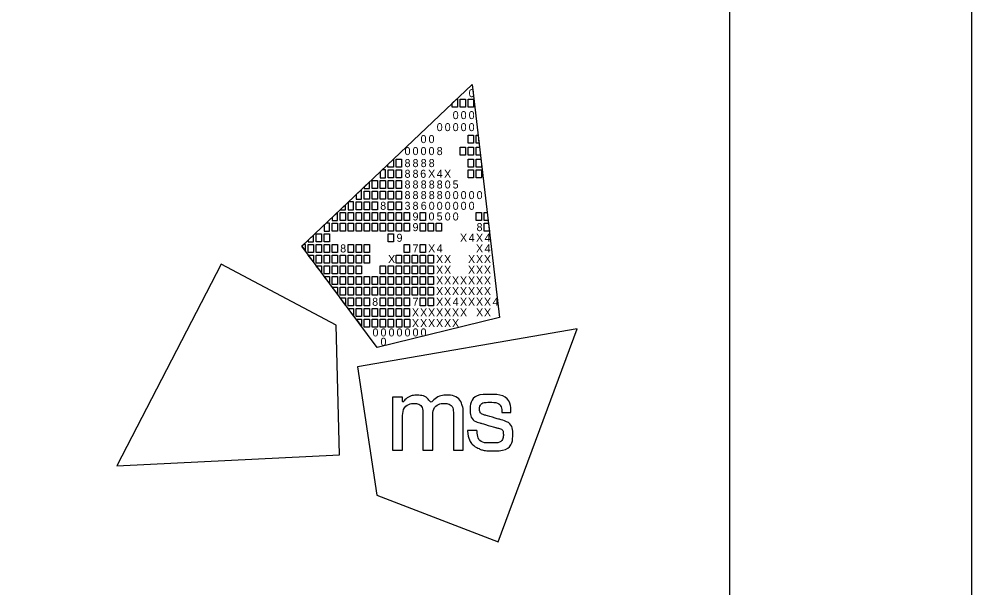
# Model space of a CAD drawing. Extents: x 0 to 34, y 0 to 22.
# Drawn here: x 32.034 to 34, y 3.547 to 4.721 of the extents above; entities that cross this region are included whole.
import ezdxf

# ---------------------------------------------------------------- set-up
doc = ezdxf.new("R2010")
doc.units = 0
for name, color, linetype in [('SH_Border', 7, 'Continuous'), ('SH_Cut_Line', 7, 'Continuous'), ('SH_Data', 7, 'Continuous')]:
    doc.layers.add(name, color=color, linetype=linetype)

msp = doc.modelspace()

# ---------------------------------------------------------------- linework, layer by layer
at = {"layer": 'SH_Border'}
for p, q in [((32.6175, 4.2519), (32.9688, 4.5861)), ((32.9688, 4.5861), (32.9688, 4.5861)), ((32.9688, 4.5861), (33.0253, 4.1052)), ((32.773, 4.043), (32.6175, 4.2519)), ((33.0253, 4.1052), (32.773, 4.043))]:
    msp.add_line(p, q, dxfattribs=at)
for points in [[(1.5, 21.5), (33.5, 21.5), (33.5, 0.5), (1.5, 0.5)], [(32.9279, 4.5472), (32.9369, 4.5558), (32.9389, 4.5558), (32.9389, 4.5393), (32.9279, 4.5393)], [(32.9444, 4.5558), (32.9554, 4.5558), (32.9554, 4.5393), (32.9444, 4.5393)], [(32.9609, 4.5558), (32.9719, 4.5558), (32.9719, 4.5393), (32.9609, 4.5393)], [(32.9606, 4.4815), (32.9716, 4.4815), (32.9716, 4.465), (32.9606, 4.465)], [(32.9771, 4.4815), (32.9811, 4.4815), (32.983, 4.465), (32.9771, 4.465)], [(32.9441, 4.4567), (32.9551, 4.4567), (32.9551, 4.4402), (32.9441, 4.4402)], [(32.9606, 4.4567), (32.9716, 4.4567), (32.9716, 4.4402), (32.9606, 4.4402)], [(32.9771, 4.4567), (32.984, 4.4567), (32.9859, 4.4402), (32.9771, 4.4402)], [(32.7953, 4.4211), (32.8064, 4.4316), (32.8064, 4.4154), (32.7953, 4.4154)], [(32.8123, 4.4319), (32.8233, 4.4319), (32.8233, 4.4154), (32.8123, 4.4154)], [(32.9606, 4.4319), (32.9716, 4.4319), (32.9716, 4.4154), (32.9606, 4.4154)], [(32.9771, 4.4319), (32.9869, 4.4319), (32.9881, 4.4218), (32.9881, 4.4154), (32.9771, 4.4154)], [(32.7958, 4.4099), (32.8068, 4.4099), (32.8068, 4.3934), (32.7958, 4.3934)], [(32.8123, 4.4099), (32.8233, 4.4099), (32.8233, 4.3934), (32.8123, 4.3934)], [(32.9606, 4.4099), (32.9716, 4.4099), (32.9716, 4.3934), (32.9606, 4.3934)], [(32.9771, 4.4099), (32.9881, 4.4099), (32.9881, 4.3934), (32.9771, 4.3934)], [(32.7627, 4.3879), (32.7737, 4.3879), (32.7737, 4.3714), (32.7627, 4.3714)], [(32.7793, 4.3879), (32.7903, 4.3879), (32.7903, 4.3714), (32.7793, 4.3714)], [(32.7958, 4.3879), (32.8068, 4.3879), (32.8068, 4.3714), (32.7958, 4.3714)], [(32.8123, 4.3879), (32.8233, 4.3879), (32.8233, 4.3714), (32.8123, 4.3714)], [(32.7462, 4.3659), (32.7572, 4.3659), (32.7572, 4.3494), (32.7462, 4.3494)], [(32.7627, 4.3659), (32.7737, 4.3659), (32.7737, 4.3494), (32.7627, 4.3494)], [(32.7793, 4.3659), (32.7903, 4.3659), (32.7903, 4.3494), (32.7793, 4.3494)], [(32.7958, 4.3659), (32.8068, 4.3659), (32.8068, 4.3494), (32.7958, 4.3494)], [(32.8123, 4.3659), (32.8233, 4.3659), (32.8233, 4.3494), (32.8123, 4.3494)], [(32.7297, 4.3439), (32.7407, 4.3439), (32.7407, 4.3273), (32.7297, 4.3273)], [(32.7462, 4.3439), (32.7572, 4.3439), (32.7572, 4.3273), (32.7462, 4.3273)], [(32.7627, 4.3439), (32.7737, 4.3439), (32.7737, 4.3273), (32.7627, 4.3273)], [(32.7958, 4.3439), (32.8068, 4.3439), (32.8068, 4.3273), (32.7958, 4.3273)], [(32.8123, 4.3439), (32.8233, 4.3439), (32.8233, 4.3273), (32.8123, 4.3273)], [(32.6967, 4.3218), (32.7077, 4.3218), (32.7077, 4.3053), (32.6967, 4.3053)], [(32.7132, 4.3218), (32.7242, 4.3218), (32.7242, 4.3053), (32.7132, 4.3053)], [(32.7297, 4.3218), (32.7407, 4.3218), (32.7407, 4.3053), (32.7297, 4.3053)], [(32.7462, 4.3218), (32.7572, 4.3218), (32.7572, 4.3053), (32.7462, 4.3053)], [(32.7627, 4.3218), (32.7737, 4.3218), (32.7737, 4.3053), (32.7627, 4.3053)], [(32.7793, 4.3218), (32.7903, 4.3218), (32.7903, 4.3053), (32.7793, 4.3053)], [(32.7958, 4.3218), (32.8068, 4.3218), (32.8068, 4.3053), (32.7958, 4.3053)], [(32.8123, 4.3218), (32.8233, 4.3218), (32.8233, 4.3053), (32.8123, 4.3053)], [(32.8288, 4.3218), (32.8398, 4.3218), (32.8398, 4.3053), (32.8288, 4.3053)], [(32.8618, 4.3218), (32.8728, 4.3218), (32.8728, 4.3053), (32.8618, 4.3053)], [(32.9771, 4.3218), (32.9881, 4.3218), (32.9881, 4.3053), (32.9771, 4.3053)], [(32.9935, 4.3218), (32.9998, 4.3218), (33.0018, 4.3053), (32.9935, 4.3053)], [(32.6802, 4.2998), (32.6912, 4.2998), (32.6912, 4.2833), (32.6802, 4.2833)], [(32.6967, 4.2998), (32.7077, 4.2998), (32.7077, 4.2833), (32.6967, 4.2833)], [(32.7132, 4.2998), (32.7242, 4.2998), (32.7242, 4.2833), (32.7132, 4.2833)], [(32.7297, 4.2998), (32.7407, 4.2998), (32.7407, 4.2833), (32.7297, 4.2833)], [(32.7462, 4.2998), (32.7572, 4.2998), (32.7572, 4.2833), (32.7462, 4.2833)], [(32.7627, 4.2998), (32.7737, 4.2998), (32.7737, 4.2833), (32.7627, 4.2833)], [(32.7793, 4.2998), (32.7903, 4.2998), (32.7903, 4.2833), (32.7793, 4.2833)], [(32.7958, 4.2998), (32.8068, 4.2998), (32.8068, 4.2833), (32.7958, 4.2833)], [(32.8123, 4.2998), (32.8233, 4.2998), (32.8233, 4.2833), (32.8123, 4.2833)], [(32.8288, 4.2998), (32.8398, 4.2998), (32.8398, 4.2833), (32.8288, 4.2833)], [(32.8618, 4.2998), (32.8728, 4.2998), (32.8728, 4.2833), (32.8618, 4.2833)], [(32.8783, 4.2998), (32.8893, 4.2998), (32.8893, 4.2833), (32.8783, 4.2833)], [(32.8947, 4.2998), (32.9057, 4.2998), (32.9057, 4.2833), (32.8947, 4.2833)], [(32.9935, 4.2998), (33.0024, 4.2998), (33.0044, 4.2833), (32.9935, 4.2833)], [(32.6471, 4.2778), (32.6581, 4.2778), (32.6581, 4.2613), (32.6471, 4.2613)], [(32.6637, 4.2778), (32.6747, 4.2778), (32.6747, 4.2613), (32.6637, 4.2613)], [(32.7958, 4.2778), (32.8068, 4.2778), (32.8068, 4.2613), (32.7958, 4.2613)], [(32.6306, 4.2558), (32.6416, 4.2558), (32.6416, 4.2393), (32.6306, 4.2393)], [(32.6471, 4.2558), (32.6581, 4.2558), (32.6581, 4.2393), (32.6471, 4.2393)], [(32.6637, 4.2558), (32.6747, 4.2558), (32.6747, 4.2393), (32.6637, 4.2393)], [(32.6802, 4.2558), (32.6912, 4.2558), (32.6912, 4.2393), (32.6802, 4.2393)], [(32.7132, 4.2558), (32.7242, 4.2558), (32.7242, 4.2393), (32.7132, 4.2393)], [(32.7297, 4.2558), (32.7407, 4.2558), (32.7407, 4.2393), (32.7297, 4.2393)], [(32.7462, 4.2558), (32.7572, 4.2558), (32.7572, 4.2393), (32.7462, 4.2393)], [(32.8288, 4.2558), (32.8398, 4.2558), (32.8398, 4.2393), (32.8288, 4.2393)], [(32.8618, 4.2558), (32.8728, 4.2558), (32.8728, 4.2393), (32.8618, 4.2393)], [(32.6306, 4.2338), (32.6416, 4.2338), (32.6416, 4.22)], [(32.6471, 4.2338), (32.6581, 4.2338), (32.6581, 4.2173), (32.6471, 4.2173)], [(32.6637, 4.2338), (32.6747, 4.2338), (32.6747, 4.2173), (32.6637, 4.2173)], [(32.6802, 4.2338), (32.6912, 4.2338), (32.6912, 4.2173), (32.6802, 4.2173)], [(32.6967, 4.2338), (32.7077, 4.2338), (32.7077, 4.2173), (32.6967, 4.2173)], [(32.7132, 4.2338), (32.7242, 4.2338), (32.7242, 4.2173), (32.7132, 4.2173)], [(32.7297, 4.2338), (32.7407, 4.2338), (32.7407, 4.2173), (32.7297, 4.2173)], [(32.7462, 4.2338), (32.7572, 4.2338), (32.7572, 4.2173), (32.7462, 4.2173)], [(32.8123, 4.2338), (32.8233, 4.2338), (32.8233, 4.2173), (32.8123, 4.2173)], [(32.8288, 4.2338), (32.8398, 4.2338), (32.8398, 4.2173), (32.8288, 4.2173)], [(32.8453, 4.2338), (32.8563, 4.2338), (32.8563, 4.2173), (32.8453, 4.2173)], [(32.8618, 4.2338), (32.8728, 4.2338), (32.8728, 4.2173), (32.8618, 4.2173)], [(32.8783, 4.2338), (32.8893, 4.2338), (32.8893, 4.2173), (32.8783, 4.2173)], [(32.6471, 4.2117), (32.6581, 4.2117), (32.6581, 4.198)], [(32.6637, 4.2117), (32.6747, 4.2117), (32.6747, 4.1952), (32.6637, 4.1952)], [(32.6802, 4.2117), (32.6912, 4.2117), (32.6912, 4.1952), (32.6802, 4.1952)], [(32.6967, 4.2117), (32.7077, 4.2117), (32.7077, 4.1952), (32.6967, 4.1952)], [(32.7132, 4.2117), (32.7242, 4.2117), (32.7242, 4.1952), (32.7132, 4.1952)], [(32.7297, 4.2117), (32.7407, 4.2117), (32.7407, 4.1952), (32.7297, 4.1952)], [(32.7793, 4.2117), (32.7903, 4.2117), (32.7903, 4.1952), (32.7793, 4.1952)], [(32.7958, 4.2117), (32.8068, 4.2117), (32.8068, 4.1952), (32.7958, 4.1952)], [(32.8123, 4.2117), (32.8233, 4.2117), (32.8233, 4.1952), (32.8123, 4.1952)], [(32.8288, 4.2117), (32.8398, 4.2117), (32.8398, 4.1952), (32.8288, 4.1952)], [(32.8453, 4.2117), (32.8563, 4.2117), (32.8563, 4.1952), (32.8453, 4.1952)], [(32.8618, 4.2117), (32.8728, 4.2117), (32.8728, 4.1952), (32.8618, 4.1952)], [(32.8783, 4.2117), (32.8893, 4.2117), (32.8893, 4.1952), (32.8783, 4.1952)], [(32.6637, 4.1897), (32.6747, 4.1897), (32.6747, 4.176)], [(32.6747, 4.1897), (32.6747, 4.1897), (32.6747, 4.1897)], [(32.6802, 4.1897), (32.6912, 4.1897), (32.6912, 4.1732), (32.6802, 4.1732)], [(32.6967, 4.1897), (32.7077, 4.1897), (32.7077, 4.1732), (32.6967, 4.1732)], [(32.7132, 4.1897), (32.7242, 4.1897), (32.7242, 4.1732), (32.7132, 4.1732)], [(32.7297, 4.1897), (32.7407, 4.1897), (32.7407, 4.1732), (32.7297, 4.1732)], [(32.7462, 4.1897), (32.7572, 4.1897), (32.7572, 4.1732), (32.7462, 4.1732)], [(32.7627, 4.1897), (32.7737, 4.1897), (32.7737, 4.1732), (32.7627, 4.1732)], [(32.7793, 4.1897), (32.7903, 4.1897), (32.7903, 4.1732), (32.7793, 4.1732)], [(32.7958, 4.1897), (32.8068, 4.1897), (32.8068, 4.1732), (32.7958, 4.1732)], [(32.8123, 4.1897), (32.8233, 4.1897), (32.8233, 4.1732), (32.8123, 4.1732)], [(32.8288, 4.1897), (32.8398, 4.1897), (32.8398, 4.1732), (32.8288, 4.1732)], [(32.8453, 4.1897), (32.8563, 4.1897), (32.8563, 4.1732), (32.8453, 4.1732)], [(32.8618, 4.1897), (32.8728, 4.1897), (32.8728, 4.1732), (32.8618, 4.1732)], [(32.8783, 4.1897), (32.8893, 4.1897), (32.8893, 4.1732), (32.8783, 4.1732)], [(32.6802, 4.1677), (32.6912, 4.1677), (32.6912, 4.154)], [(32.6967, 4.1677), (32.7077, 4.1677), (32.7077, 4.1512), (32.6967, 4.1512)], [(32.7132, 4.1677), (32.7242, 4.1677), (32.7242, 4.1512), (32.7132, 4.1512)], [(32.7297, 4.1677), (32.7407, 4.1677), (32.7407, 4.1512), (32.7297, 4.1512)], [(32.7462, 4.1677), (32.7572, 4.1677), (32.7572, 4.1512), (32.7462, 4.1512)], [(32.7627, 4.1677), (32.7737, 4.1677), (32.7737, 4.1512), (32.7627, 4.1512)], [(32.7793, 4.1677), (32.7903, 4.1677), (32.7903, 4.1512), (32.7793, 4.1512)], [(32.7958, 4.1677), (32.8068, 4.1677), (32.8068, 4.1512), (32.7958, 4.1512)], [(32.8123, 4.1677), (32.8233, 4.1677), (32.8233, 4.1512), (32.8123, 4.1512)], [(32.8288, 4.1677), (32.8398, 4.1677), (32.8398, 4.1512), (32.8288, 4.1512)], [(32.8453, 4.1677), (32.8563, 4.1677), (32.8563, 4.1512), (32.8453, 4.1512)], [(32.8618, 4.1677), (32.8728, 4.1677), (32.8728, 4.1512), (32.8618, 4.1512)], [(32.8783, 4.1677), (32.8893, 4.1677), (32.8893, 4.1512), (32.8783, 4.1512)], [(32.7077, 4.1305), (32.6965, 4.1457), (32.7077, 4.1457)], [(32.7132, 4.1457), (32.7242, 4.1457), (32.7242, 4.1292), (32.7132, 4.1292)], [(32.7297, 4.1457), (32.7407, 4.1457), (32.7407, 4.1292), (32.7297, 4.1292)], [(32.7462, 4.1457), (32.7572, 4.1457), (32.7572, 4.1292), (32.7462, 4.1292)], [(32.7793, 4.1457), (32.7903, 4.1457), (32.7903, 4.1292), (32.7793, 4.1292)], [(32.7958, 4.1457), (32.8068, 4.1457), (32.8068, 4.1292), (32.7958, 4.1292)], [(32.8123, 4.1457), (32.8233, 4.1457), (32.8233, 4.1292), (32.8123, 4.1292)], [(32.8288, 4.1457), (32.8398, 4.1457), (32.8398, 4.1292), (32.8288, 4.1292)], [(32.8618, 4.1457), (32.8728, 4.1457), (32.8728, 4.1292), (32.8618, 4.1292)], [(32.8783, 4.1457), (32.8893, 4.1457), (32.8893, 4.1292), (32.8783, 4.1292)], [(32.724, 4.1082), (32.7132, 4.1237), (32.7242, 4.1237)], [(32.7297, 4.1237), (32.7407, 4.1237), (32.7407, 4.1072), (32.7297, 4.1072)], [(32.7462, 4.1237), (32.7572, 4.1237), (32.7572, 4.1072), (32.7462, 4.1072)], [(32.7627, 4.1237), (32.7737, 4.1237), (32.7737, 4.1072), (32.7627, 4.1072)], [(32.7793, 4.1237), (32.7903, 4.1237), (32.7903, 4.1072), (32.7793, 4.1072)], [(32.7958, 4.1237), (32.8068, 4.1237), (32.8068, 4.1072), (32.7958, 4.1072)], [(32.8123, 4.1237), (32.8233, 4.1237), (32.8233, 4.1072), (32.8123, 4.1072)], [(32.8288, 4.1237), (32.8398, 4.1237), (32.8398, 4.1072), (32.8288, 4.1072)], [(32.7302, 4.1017), (32.7407, 4.1017), (32.7408, 4.0875)], [(32.7463, 4.1017), (32.7573, 4.1017), (32.7573, 4.0852), (32.7463, 4.0852)], [(32.763, 4.1017), (32.774, 4.1017), (32.774, 4.0852), (32.763, 4.0852)], [(32.7794, 4.1017), (32.7904, 4.1017), (32.7904, 4.0852), (32.7794, 4.0852)], [(32.796, 4.1017), (32.807, 4.1017), (32.807, 4.0852), (32.796, 4.0852)], [(32.8129, 4.1017), (32.8239, 4.1017), (32.8239, 4.0851), (32.8129, 4.0851)], [(32.8296, 4.1017), (32.8406, 4.1017), (32.8406, 4.0851), (32.8296, 4.0851)]]:
    msp.add_lwpolyline(points, close=True, dxfattribs=at)
for points in [[(32.7903, 4.4099), (32.7836, 4.4099), (32.7793, 4.4058), (32.7793, 4.3934), (32.7903, 4.3934), (32.7903, 4.4099)], [(32.7572, 4.3849), (32.7462, 4.3744), (32.7462, 4.3714), (32.7572, 4.3714), (32.7572, 4.3849)], [(32.7407, 4.3691), (32.7297, 4.3587), (32.7297, 4.3494), (32.7407, 4.3494), (32.7407, 4.3691)], [(32.7077, 4.3377), (32.6968, 4.3273), (32.7077, 4.3273), (32.7077, 4.3377)], [(32.7242, 4.3439), (32.7141, 4.3439), (32.7132, 4.343), (32.7132, 4.3273), (32.7242, 4.3273), (32.7242, 4.3439)], [(32.6912, 4.322), (32.6802, 4.3115), (32.6802, 4.3053), (32.6912, 4.3053), (32.6912, 4.322)], [(32.6747, 4.2998), (32.6679, 4.2998), (32.6637, 4.2958), (32.6637, 4.2833), (32.6747, 4.2833), (32.6747, 4.2998)], [(32.6416, 4.2749), (32.6306, 4.2644), (32.6306, 4.2613), (32.6416, 4.2613), (32.6416, 4.2749)], [(32.6251, 4.2558), (32.6216, 4.2558), (32.6175, 4.2519), (32.6251, 4.2417), (32.6251, 4.2558)], [(32.4512, 4.2149), (32.2359, 3.7988), (32.6956, 3.8215), (32.6884, 4.0892), (32.4512, 4.2149)], [(33.0229, 3.6422), (33.1859, 4.0814), (32.7324, 4.0029), (32.7722, 3.7381), (33.0229, 3.6422)]]:
    msp.add_lwpolyline(points, dxfattribs=at)
for points in [[(32.8048, 3.8315), (32.8048, 3.8315), (32.8048, 3.9409), (32.8048, 3.9409), (32.8048, 3.9409), (32.8255, 3.9409), (32.8255, 3.9409), (32.8255, 3.9409), (32.8255, 3.9297), (32.8255, 3.9297), (32.8346, 3.9399), (32.8457, 3.9445), (32.8555, 3.9445), (32.8688, 3.9445), (32.8791, 3.9372), (32.8837, 3.9266), (32.8915, 3.9381), (32.905, 3.9446), (32.9166, 3.9446), (32.9325, 3.9446), (32.9451, 3.935), (32.9494, 3.9213), (32.9494, 3.9212), (32.9494, 3.9212), (32.9494, 3.9212), (32.9501, 3.919), (32.9506, 3.9172), (32.9506, 3.9071), (32.9506, 3.9071), (32.9506, 3.8314), (32.9506, 3.8314), (32.9506, 3.8314), (32.9303, 3.8314), (32.9303, 3.8314), (32.9303, 3.8314), (32.9303, 3.9048), (32.9303, 3.9048), (32.9303, 3.9201), (32.9219, 3.9274), (32.911, 3.9274), (32.8995, 3.9274), (32.8879, 3.9171), (32.8879, 3.9001), (32.8879, 3.9001), (32.8879, 3.8315), (32.8879, 3.8315), (32.8879, 3.8315), (32.8674, 3.8315), (32.8674, 3.8315), (32.8674, 3.8315), (32.8674, 3.9059), (32.8674, 3.9059), (32.8674, 3.9203), (32.8588, 3.9274), (32.8496, 3.9274), (32.8384, 3.9274), (32.8254, 3.917), (32.8254, 3.8962), (32.8254, 3.8962), (32.8254, 3.8315), (32.8254, 3.8315), (32.8254, 3.8315), (32.8048, 3.8315), (32.8048, 3.8315)], [(32.9595, 3.8709), (32.9595, 3.8709), (32.9595, 3.8717), (32.9595, 3.8717), (32.9595, 3.8717), (32.9603, 3.8717), (32.9603, 3.8717), (32.9603, 3.8717), (32.9783, 3.8717), (32.9783, 3.8717), (32.9783, 3.8717), (32.9789, 3.8717), (32.9789, 3.8717), (32.9789, 3.8717), (32.979, 3.871), (32.979, 3.871), (32.9803, 3.8554), (32.9887, 3.846), (33.009, 3.846), (33.0273, 3.846), (33.0333, 3.8554), (33.0333, 3.8631), (33.0333, 3.8732), (33.0256, 3.8758), (33.0175, 3.878), (33.0175, 3.878), (32.987, 3.8867), (32.987, 3.8867), (32.972, 3.8909), (32.9648, 3.9019), (32.9648, 3.9142), (32.9648, 3.9303), (32.9768, 3.9462), (33.0052, 3.9462), (33.0348, 3.9462), (33.0489, 3.9285), (33.0489, 3.9095), (33.0489, 3.9095), (33.0489, 3.9087), (33.0489, 3.9087), (33.0489, 3.9087), (33.0482, 3.9087), (33.0482, 3.9087), (33.0482, 3.9087), (33.0312, 3.9087), (33.0312, 3.9087), (33.0312, 3.9087), (33.0305, 3.9087), (33.0305, 3.9087), (33.0305, 3.9087), (33.0305, 3.9094), (33.0305, 3.9094), (33.0301, 3.9208), (33.0226, 3.93), (33.0056, 3.93), (32.9891, 3.93), (32.9843, 3.9218), (32.9843, 3.9157), (32.9843, 3.9108), (32.9869, 3.9059), (32.9959, 3.9033), (32.9959, 3.9033), (33.0255, 3.8948), (33.0255, 3.8948), (33.0462, 3.8889), (33.0527, 3.8777), (33.0527, 3.8639), (33.0527, 3.8462), (33.041, 3.8298), (33.0087, 3.8298), (32.9952, 3.8298), (32.9877, 3.8321), (32.9823, 3.8348), (32.969, 3.8414), (32.9609, 3.8536), (32.9595, 3.8709)]]:
    msp.add_open_spline(points, degree=3, dxfattribs=at)
at = {"layer": 'SH_Cut_Line'}
msp.add_lwpolyline([(0, 0), (34, 0), (34, 22), (0, 22)], close=True, dxfattribs=at)
at = {"layer": 'SH_Data'}
msp.add_line((32.75, 4), (32.75, 4), dxfattribs=at)

# ---------------------------------------------------------------- texts
at = {"layer": 'SH_Border'}
for s, p in [('0', (32.9617, 4.5597)), ('0', (32.9288, 4.5145)), ('0', (32.9452, 4.5145)), ('0', (32.9617, 4.5145)), ('0', (32.8958, 4.4897)), ('0', (32.9123, 4.4897)), ('0', (32.9288, 4.4897)), ('0', (32.9452, 4.4897)), ('0', (32.9617, 4.4897)), ('0', (32.8625, 4.465)), ('0', (32.879, 4.465)), ('0', (32.8295, 4.4402)), ('0', (32.846, 4.4402)), ('0', (32.8625, 4.4402)), ('0', (32.879, 4.4402)), ('8', (32.8958, 4.4402)), ('8', (32.8295, 4.4154)), ('8', (32.846, 4.4154)), ('8', (32.8628, 4.4154)), ('8', (32.8793, 4.4154)), ('8', (32.8295, 4.3934)), ('8', (32.846, 4.3934)), ('6', (32.8618, 4.3934)), ('X', (32.8781, 4.3934)), ('4', (32.8958, 4.3934)), ('X', (32.911, 4.3934)), ('8', (32.8295, 4.3713)), ('8', (32.846, 4.3713)), ('8', (32.8628, 4.3713)), ('8', (32.8794, 4.3713)), ('8', (32.8958, 4.3713)), ('0', (32.9123, 4.3713)), ('5', (32.9287, 4.3713)), ('8', (32.8295, 4.3494)), ('8', (32.846, 4.3494)), ('8', (32.8628, 4.3494)), ('8', (32.8794, 4.3494)), ('8', (32.8958, 4.3494)), ('0', (32.9123, 4.3494)), ('0', (32.9288, 4.3494)), ('0', (32.9452, 4.3494)), ('0', (32.9617, 4.3494)), ('0', (32.9782, 4.3494)), ('8', (32.7793, 4.3273)), ('3', (32.8295, 4.3273)), ('8', (32.846, 4.3273)), ('6', (32.8629, 4.3273)), ('0', (32.8793, 4.3273)), ('0', (32.8958, 4.3273)), ('0', (32.9123, 4.3273)), ('0', (32.9288, 4.3273)), ('0', (32.9452, 4.3273)), ('0', (32.9617, 4.3273)), ('9', (32.846, 4.3053)), ('0', (32.879, 4.3053)), ('5', (32.8957, 4.3053)), ('0', (32.9123, 4.3053)), ('0', (32.9288, 4.3053)), ('9', (32.846, 4.2833)), ('8', (32.9781, 4.2833)), ('9', (32.813, 4.2613)), ('X', (32.9439, 4.2613)), ('4', (32.9617, 4.2613)), ('X', (32.9769, 4.2613)), ('4', (32.9946, 4.2613)), ('8', (32.6967, 4.2393)), ('7', (32.846, 4.2393)), ('X', (32.8781, 4.2393)), ('4', (32.8958, 4.2393)), ('X', (32.9769, 4.2393)), ('4', (32.9946, 4.2393)), ('X', (32.7955, 4.2173)), ('X', (32.8945, 4.2173)), ('X', (32.911, 4.2173)), ('X', (32.9604, 4.2173)), ('X', (32.9769, 4.2173)), ('X', (32.9933, 4.2173)), ('X', (32.8945, 4.1952)), ('X', (32.911, 4.1952)), ('X', (32.9604, 4.1952)), ('X', (32.9769, 4.1952)), ('X', (32.9933, 4.1952)), ('X', (32.8945, 4.1732)), ('X', (32.911, 4.1732)), ('X', (32.9274, 4.1732)), ('X', (32.9439, 4.1732)), ('X', (32.9604, 4.1732)), ('X', (32.9769, 4.1732)), ('X', (32.9933, 4.1732)), ('X', (32.8945, 4.1512)), ('X', (32.911, 4.1512)), ('X', (32.9274, 4.1512)), ('X', (32.9439, 4.1512)), ('X', (32.9604, 4.1512)), ('X', (32.9769, 4.1512)), ('X', (32.9933, 4.1512)), ('8', (32.7627, 4.1292)), ('7', (32.846, 4.1292)), ('X', (32.8945, 4.1292)), ('X', (32.911, 4.1292)), ('4', (32.9288, 4.1292)), ('X', (32.9439, 4.1292)), ('X', (32.9604, 4.1292)), ('X', (32.9769, 4.1292)), ('X', (32.9933, 4.1292)), ('4', (33.0111, 4.1292)), ('X', (32.8447, 4.1072)), ('X', (32.8616, 4.1072)), ('X', (32.878, 4.1072)), ('X', (32.8945, 4.1072)), ('X', (32.911, 4.1072)), ('X', (32.9274, 4.1072)), ('X', (32.9439, 4.1072)), ('X', (32.9771, 4.1072)), ('X', (32.9933, 4.1072)), ('X', (32.8447, 4.0851)), ('X', (32.8616, 4.0851)), ('X', (32.878, 4.0851)), ('X', (32.8945, 4.0851)), ('X', (32.911, 4.0851)), ('X', (32.9274, 4.0851)), ('0', (32.7634, 4.0659)), ('0', (32.7799, 4.0659)), ('0', (32.7965, 4.0659)), ('0', (32.813, 4.0659)), ('0', (32.8295, 4.0659)), ('0', (32.846, 4.0659)), ('0', (32.8625, 4.0659)), ('0', (32.7799, 4.0467))]:
    msp.add_text(s, height=0.0165, rotation=360, dxfattribs=at).set_placement(p)

doc.saveas('drawing.dxf')
